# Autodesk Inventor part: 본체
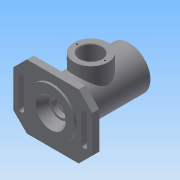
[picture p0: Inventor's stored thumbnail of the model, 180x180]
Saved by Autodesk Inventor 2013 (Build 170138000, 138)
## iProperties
Created: 2017-10
Part Number: 본체
Material: 일반
Document SubType Name: Modeling
Designer: Administrator
Density: 1 g/cm^3
Author: Administrator
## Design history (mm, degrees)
sketch "스케치1"
  geometry: L1 (38, -47)-(-38, -47); L2 (-58, -27)-(-58, 27); L3 (-38, 47)-(38, 47); L4 (58, 27)-(58, -27); L5 (58, -47)-(-58, 47); L6 (-58, -47)-(58, 47); L7 (-58, 27)-(-38, 47); L8 (-58, -27)-(-38, -47); L9 (38, -47)-(58, -27); L10 (58, 27)-(38, 47); 1 further point
  constraints: 20 end point, 8 point on line, 2 midpoint, 2 parallel, 1 horizontal, 1 perpendicular
  dimensions: "d0" = 116 distance of L5.end L6.end; "d2" = 94 distance between parallel lines of L1 L3; "d3" = 20 distance of L2.end L5.end; "d4" = 20 distance of L3.start L5.end (= d3); "d5" = 20 distance of L2.start L6.start (= d3); "d6" = 20 distance of L1.end L6.start (= d5); "d7" = 20 distance of L1.start L5.start (= d3); "d8" = 20 distance of L4.end L5.start (= d7); "d9" = 20 distance of L4.start L6.end (= d3); "d10" = 20 distance of L3.end L6.end (= d9)
extrude "돌출1" new body sketch "스케치1" distance "d11" = 10; taper "d12" = 0 deg
sketch "스케치2"
  geometry: C1 r 35 at (0, 0); 1 further point
  constraints: 1 centre point, 1 coincident
  dimensions: "d13" = 70 diameter of C1
extrude "돌출2" join sketch "스케치2" distance "d15" = 3; taper "d16" = 0 deg
sketch "스케치3"
  geometry: L1 (-27, -10)-(27, -10) reference; L2 (0, -10)-(0, -112); L3 (0, -112)-(31, -112); L4 (31, -112)-(31, -10); L5 (31, -10)-(0, -10); 1 further point
  constraints: 8 end point, 2 parallel, 2 perpendicular, 1 midpoint
  dimensions: "d17" = 102 distance of L2.start L2.end; "d19" = 31 distance of L2.end L3.end
revolve "회전1" sketch "스케치3" stored, may be unused: angle "d20" = 90 deg
sketch "스케치4"
  geometry: L1 (-42, -20)-(-42, 20); L2 (-50, 20)-(-50, -20); L3 (-50, -20)-(-42, 20); L4 (-42, -20)-(-50, 20); C1 r 35 at (0, 0) reference; A1 r 4 centre (-46, 20) between (-42, 20) and (-50, 20); A2 r 4 centre (-46, -20) between (-50, -20) and (-42, -20); 4 further points
  constraints: 8 end point, 4 midpoint, 4 point on circle, 2 centre point, 2 tangent, 1 coincident, 1 horizontal alignment, 1 parallel, 1 vertical alignment
  dimensions: "d22" = 8 distance of L1.end L2.start; "d24" = 40 distance of L2.start L2.end; "d27" = 4 radius of A1; "d28" = 4 radius of A2; "d29" = 46 distance of C1.centre point (-46, 0)
extrude "돌출3" cut sketch "스케치4" stored distance "d30" = 3; taper "d31" = 0 deg
node "작업 평면1"
sketch "스케치5"
  geometry: L1 (38, 0)-(-38, 0) reference; L2 (-31, -112)-(31, -112) reference; C1 r 25 at (0, -56); 2 further points
  constraints: 1 centre point, 1 midpoint, 1 vertical alignment
  dimensions: "d33" = 50 diameter of C1; "d35" = 56 distance from line of L2 C1.centre
extrude "돌출4" join sketch "스케치5" stored distance "d36" = 3; taper "d37" = 0 deg
sketch "스케치6"
  geometry: L1 (22, 3)-(16, -11); L2 (16, -11)-(12.904, -11); L3 (12.5, -11.7)-(12.5, -18); L4 (12.2, -18.3)-(10, -18.3); L5 (10, -18.3)-(10, -21); L6 (10, -21)-(13.5, -21); L7 (16.5, -24)-(16.5, -26); L8 (16.5, -26)-(17.2, -26); L9 (17.5, -26.3)-(17.5, -37); L10 (17.5, -37)-(23, -37); L11 (26, -40)-(26, -72); L12 (23, -75)-(17.5, -75); L13 (17.5, -75)-(17.5, -86); L14 (17.5, -86)-(18.5, -86); L15 (18.5, -86)-(18.5, -87.75); L16 (18.5, -87.75)-(17.5, -87.75); L17 (17.5, -87.75)-(17.5, -91); L18 (17.5, -91)-(20, -91); L19 (20, -91)-(20, -100); L20 (20, -100)-(24, -100); L21 (24, -100)-(24, -103); L22 (24, -103)-(21, -103); L23 (21, -103)-(21, -112); L24 (21, -112)-(0, -112); L25 (0, -112)-(0, 3); L26 (0, 3)-(22, 3); L27 (35, 3)-(-35, 3) reference; L28 (12.5, -11.7)-(12.904, -11); A1 r 3 centre (23, -72) between (23, -75) and (26, -72); A2 r 3 centre (23, -40) between (26, -40) and (23, -37); A3 r 0.3 centre (17.2, -26.3) between (17.5, -26.3) and (17.2, -26); A4 r 3 centre (13.5, -24) between (16.5, -24) and (13.5, -21); A5 r 0.3 centre (12.2, -18) between (12.2, -18.3) and (12.5, -18); 6 further points
  constraints: 54 end point, 23 perpendicular, 10 point on circle, 10 point on line, 10 tangent, 5 centre point, 3 equal radius, 2 horizontal, 1 collinear, 1 vertical alignment
  dimensions: "d38" = 22 distance of L25.end L1.start; "d40" = 14 vertical distance of L1.start L1.end; "d41" = 16 distance from line of L25 L1.end; "d42" = 12.5 distance between parallel lines of L25 L3; "d43" = 10 distance between parallel lines of L25 L5; "d44" = 16.5 distance between parallel lines of L25 L7; "d45" = 17.5 distance between parallel lines of L25 L9; "d46" = 26 distance between parallel lines of L25 L11; "d47" = 17.5 distance between parallel lines of L25 L13; "d48" = 18.5 distance between parallel lines of L25 L15; "d49" = 17.5 distance between parallel lines of L25 L17; "d51" = 20 distance between parallel lines of L25 L19; "d52" = 24 distance between parallel lines of L25 L21; "d53" = 21 distance between parallel lines of L25 L23; "d54" = 7.3 distance of point (12.5, -11) point (12.5, -18.3); "d55" = 2.7 distance of L4.end L5.end; "d56" = 5 distance of point (16.5, -21) L7.end; "d57" = 115 distance of L24.end L25.end; "d58" = 9 distance of L22.end L23.end; "d59" = 3 distance of L20.end L21.end; "d60" = 9 distance of L18.end L19.end; "d61" = 3.25 distance of L16.end L17.end; "d62" = 1.75 distance of L14.end L15.end; "d63" = 11 distance of L12.end L13.end; "d64" = 38 distance of point (26, -37) point (26, -75); "d65" = 3 radius of A1; "d66" = 0.3 radius of A3; "d67" = 0.7 distance of L3.start point (12.5, -11); "d68" = 30 deg angle of L3 L28
revolve "회전2" sketch "스케치6" stored, may be unused: angle "d69" = 90 deg
chamfer "모따기1" distance "d70" = 1; stored, may be unused: second distance "d71" = 2, angle "d72" = 45 deg
sketch "스케치7"
  geometry: C1 r 25 at (0, 0) reference; C2 r 16 at (0, 0); 1 further point
  constraints: 1 centre point, 1 concentric
  dimensions: "d73" = 32 diameter of C2
extrude "돌출5" cut sketch "스케치7" distance "d75" = 40; taper "d76" = 0 deg
chamfer "모따기2" distance "d77" = 1; stored, may be unused: second distance "d78" = 2, angle "d79" = 45 deg
sketch "스케치8" dims "d80" = 41
  geometry: C1 r 25 at (0, 0) reference; C2 r 17 at (0, 0) reference; 3 further points
  constraints: 2 horizontal alignment, 1 coincident, 2 other
node "작업 평면2"
sketch "스케치9"
  geometry: 2 further points
  constraints: 1 other
feature "엠보싱1" sketch "스케치9" dims "d83" = 0.5, "d84" = 0
hole "구멍1" sketch "스케치8" diameter "d85" = 2.459; stored, may be unused: countersink angle "d89" = 90 deg, drill point angle "d91" = 118 deg; dims "d86" = 6, "d87" = 4, "d88" = 2, "d90" = 8
feature "스레드1" dims "d92" = 10, "d93" = 0
node "솔리드1"
mirror "대칭1"
mirror "대칭2"
other parameters: "d32" = 47, "d82" = -86.5
